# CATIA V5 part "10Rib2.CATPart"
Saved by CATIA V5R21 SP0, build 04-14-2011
Part number: Rib1_tip
Bounding box of the stored display mesh (mm): x 0 to 6.5, y -3.709 to 3.709, z -223.75 to 3.75
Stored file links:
  F:\教程\Robotic_Arm_Arduino_Kinect\机械臂CAD\Arm_Detailed_Design\Rib2.CATPart
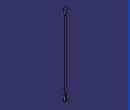
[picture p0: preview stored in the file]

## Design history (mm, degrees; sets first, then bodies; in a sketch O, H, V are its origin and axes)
Body1 (main body)
  Sketch1 on yz-plane, origin (0, 0, 0), H (0, 1, 0), V (0, 0, 1)
    arc A1 centre (0, 0) radius 3.75 from (2, -3.1721) to (-2, -3.1721) ccw
    point P1 (-2, -3.1721)
    line L1 (-2, -3.1721) -> (-2, -14)
    point P2 (-2, -14)
    line L2 (-2, -14) -> (0, -14)
    point P3 (0, -14)
    point P4 (2, -14)
    point P5 (2, -3.1721)
    line L3 (2, -3.1721) -> (2, -14)
    point P6 (0, -14)
    line L4 (2, -14) -> (0, -14)
    axis line L5 (-144.6893, -110) -> (122.6008, -110)
    construction line L6 through (0, -220) direction (0, -1)
    point P10 (-2, -216.8279)
    point P11 (-2, -206)
    point P12 (0, -206)
    point P13 (2, -206)
    point P14 (2, -216.8279)
    point P15 (0, -206)
    arc A2 centre (0, -220) radius 3.75 from (2, -216.8279) to (-2, -216.8279) cw
    line L7 (-2, -216.8279) -> (-2, -206)
    line L8 (-2, -206) -> (0, -206)
    line L9 (2, -216.8279) -> (2, -206)
    line L10 (2, -206) -> (0, -206)
    radius A1 = 3.75
    distance H L4 = 14
    distance L1 L3 = 4
    distance L5 H = 110
    vertical: L1 V
    coincidence: P3 V, P3 P6
    horizontal: L2 H, L5 H
    symmetry: P2 P4 V, P1 P5 V, L1 L3 V, P3 P6 V, L2 L4 V, V L6 L5, P1 P10 L5, P2 P11 L5, P3 P12 L5, P4 P13 L5, P5 P14 L5, P6 P15 L5, A1 A2 L5, L1 L7 L5, L2 L8 L5, L3 L9 L5, L4 L10 L5
  Pad1: profile Sketch1, direction (1, 0, 0), length 3.5
  Sketch2 on end face of Pad1, origin (3.5, 0, 0), H (0, 1, 0), V (0, 0, 1)
    circle A1 centre (0, 0) radius 1.25
    radius A1 = 1.25
  Sketch3 on face of Pad1 from Sketch1.L2, origin (0, 0, -14), H (1, 0, 0), V (0, -1, 0)
    circle A1 centre (1.75, 0) radius 1
    point P1 (1.75, 0)
    radius A1 = 1
    distance P1 V = 1.75
    coincidence: P1 H
  Pocket1: profile Sketch3, direction (0, 0, 1), length 5
  Pad2: profile Sketch2, direction (1, 0, 0), length 3
  Sketch4 on face of Pad1 from Sketch1.L10, origin (0, 0, -206), H (1, 0, 0), V (0, 1, 0)
    circle A1 centre (1.75, 0) radius 1
    point P1 (1.75, 0)
    radius A1 = 1
    distance P1 V = 1.75
    coincidence: P1 H
  Pocket2: profile Sketch4, direction (0, 0, -1), length 5
  Sketch5 on end face of Pocket2, origin (0, 0, -211), H (1, 0, 0), V (0, 1, 0)
    circle A1 centre (1.75, 0) radius 1
    point P1 (1.75, 0)
    radius A1 = 1
    distance P1 V = 1.75
    coincidence: P1 H
  Pad3: profile Sketch5, direction (0, 0, 1), up to end face of Pocket1
  Sketch6 on end face of Pad1, origin (3.5, 0, 0), H (0, 1, 0), V (0, 0, 1)
    circle A1 centre (0, -220) radius 1.25
    point P1 (0, -220)
    reference projected arc E1 centre (0, -220) radius 3.75 from (-1.875, -216.7524) to (1.875, -216.7524) ccw from edge [face of Pad1 from Sketch1.A2 | end face of Pad1]
    radius A1 = 1.25
    coincidence: P1 V
    concentricity: A1 E1
  Pad4: profile Sketch6, direction (1, 0, 0), length 3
